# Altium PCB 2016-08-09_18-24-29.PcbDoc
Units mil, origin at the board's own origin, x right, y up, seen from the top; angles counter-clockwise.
Board outline 2000 x 2400 mil, 4 copper layers (Top Layer, MidLayer1, MidLayer2, Bottom Layer); 17 components, 8 nets, 39 pads, 72 vias.
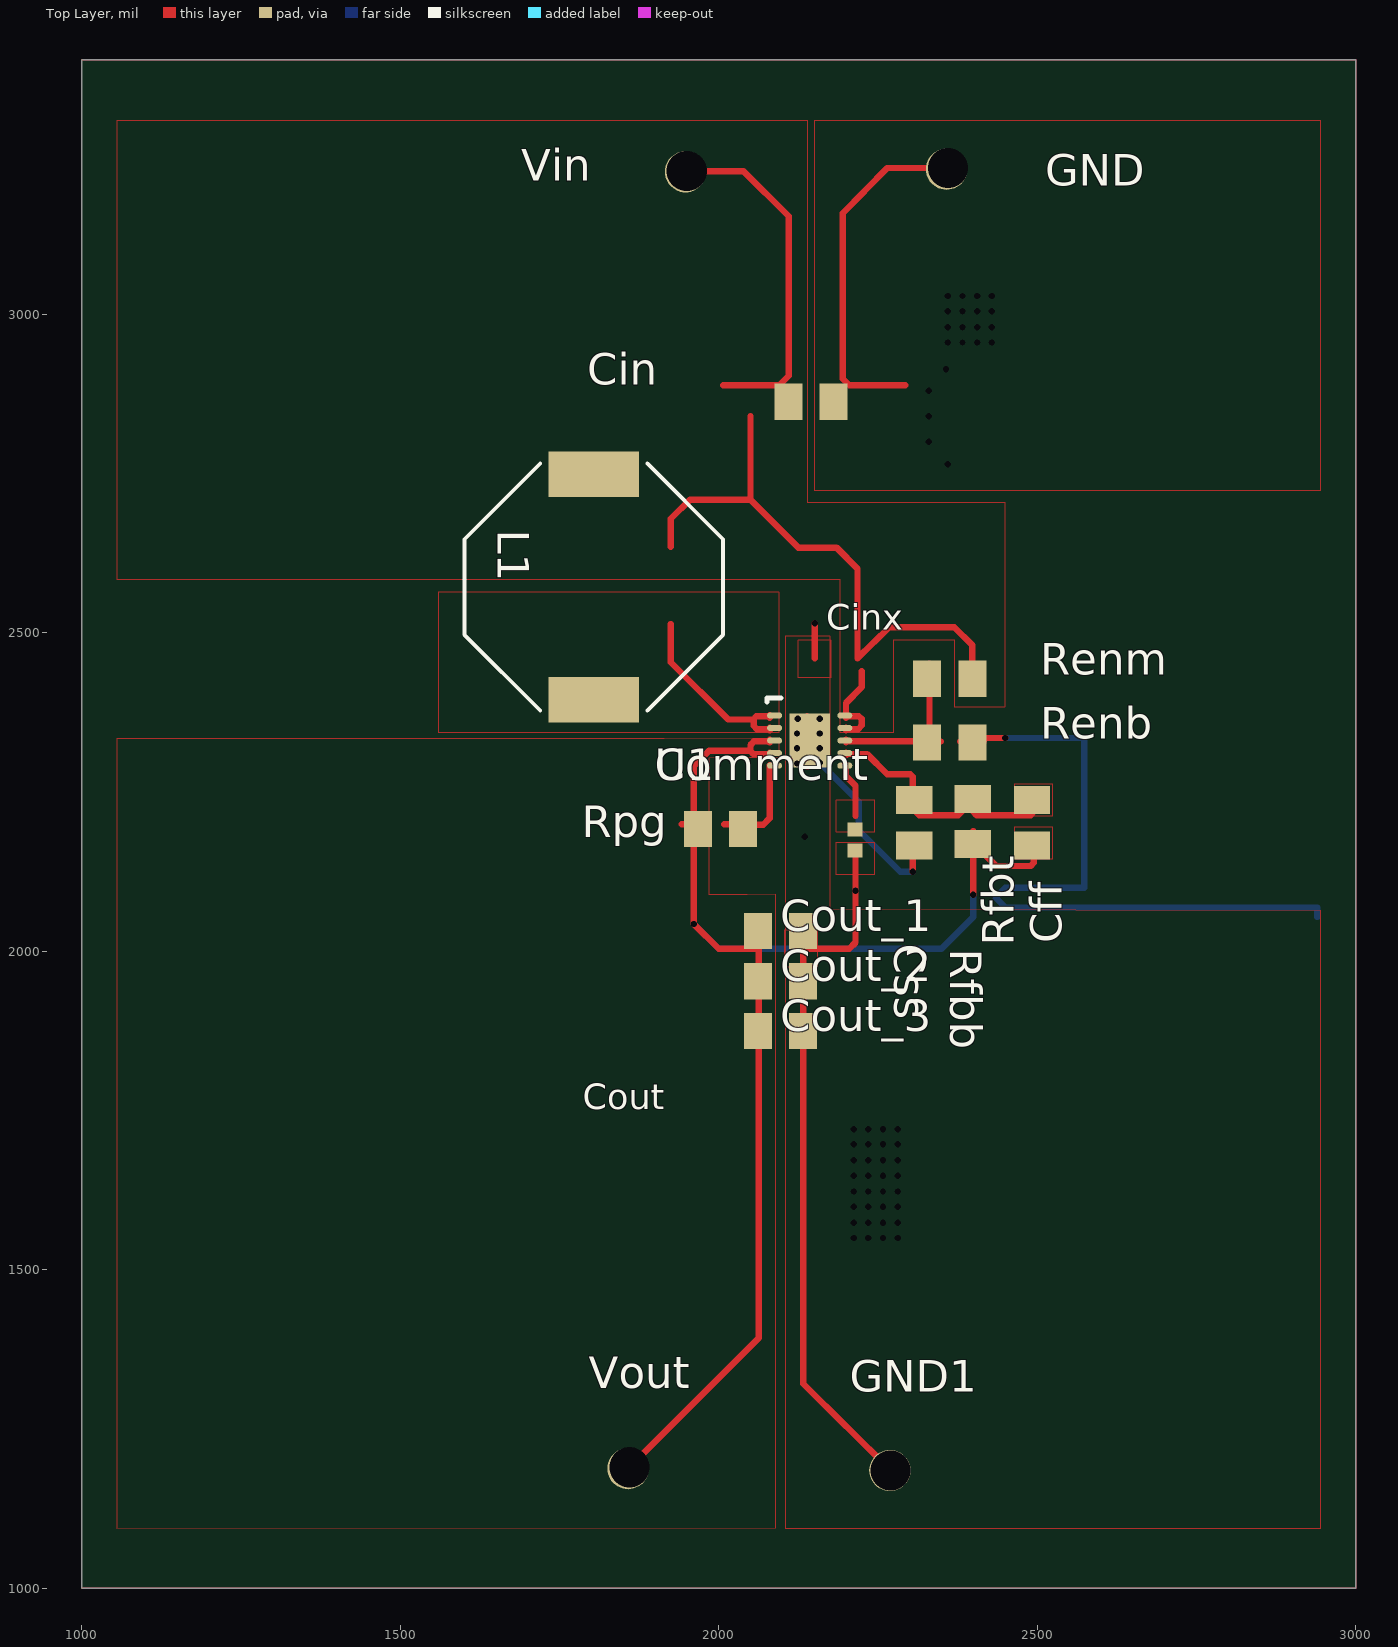
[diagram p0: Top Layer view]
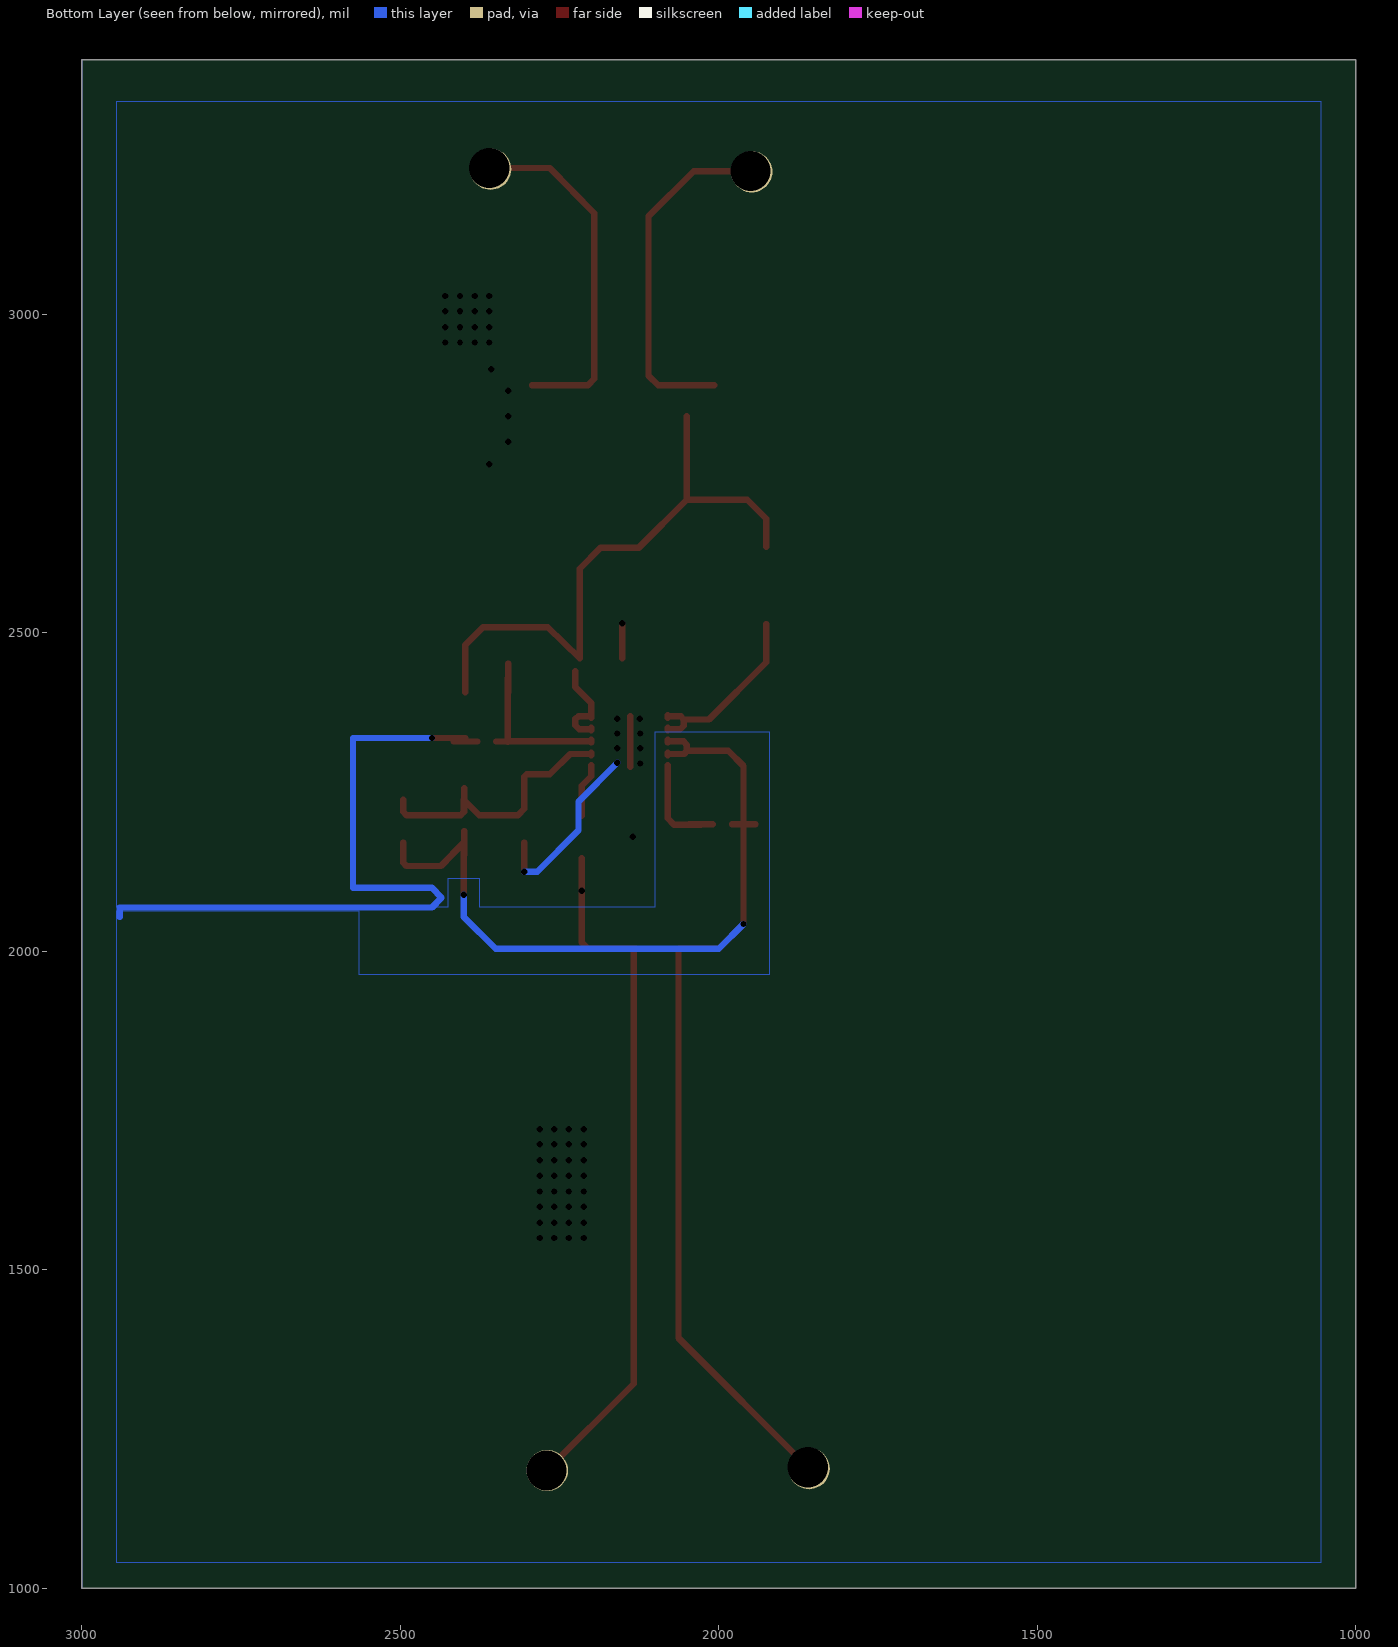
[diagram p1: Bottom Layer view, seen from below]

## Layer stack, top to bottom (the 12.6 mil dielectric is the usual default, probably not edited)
Top Layer: signal copper 1.4
Dielectric: core 12.6, FR-4, Dk 4.8
MidLayer1: signal copper 1.4
Dielectric: prepreg 12.6, FR-4, Dk 4.8
MidLayer2: signal copper 1.4
Dielectric: core 12.6, FR-4, Dk 4.8
Bottom Layer: signal copper 1.4

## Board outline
1000,1000 3000,1000 3000,3400 1000,3400

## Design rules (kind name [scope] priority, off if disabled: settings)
PlaneConnect [All] p0: scope1count=1 scope1_0_kind=Board scope1_0_value=Board scope2count=1 scope2_0_kind=Board scope2_0_value=Board commentlength=0 planeconnectstyle=Direct reliefexpansion=20 reliefentries=4 reliefconductorwidth=10 reliefairgap=10
PlaneConnect [All] p1: planeconnectstyle=Direct reliefexpansion=20 reliefentries=4 reliefconductorwidth=10 reliefairgap=10
PolygonConnect [All] p0: scope1count=1 scope1_0_kind=Board scope1_0_value=Board scope2count=1 scope2_0_kind=Board scope2_0_value=Board commentlength=0 connectstyle=Direct reliefconductorwidth=10 reliefentries=4 polygonreliefangle="90 Angle"
PolygonConnect [All] p1: connectstyle=Direct reliefconductorwidth=10 reliefentries=4 polygonreliefangle="90 Angle"

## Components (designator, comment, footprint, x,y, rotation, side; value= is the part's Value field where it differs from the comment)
Cff "" 0805 2492,2202 r90 top
Cin "" 0805 2145,2863 r0 top
Cout_1 "" 0805 2097,2032 r0 top
Cout_2 "" 0805 2097,1953 r0 top
Cout_3 "" 0805 2097,1875 r0 top
Css "" 0402 2214,2175 r270 top
GND "" TP-1502 2358,3228 r0 top
GND1 "" TP-1502 2269,1185 r0 top
L1 "" SRU1028 1804,2572 r270 top
Renb "" 0805 2363,2328 r0 top
Renm "" 0805 2363,2428 r0 top
Rfbb "" 0805 2307,2202 r270 top
Rfbt "" 0805 2399,2204 r90 top
Rpg "" 0805 2003,2192 r0 top
U1 "" DRC0010G 2143,2331 r0 top
Vin "" TP-1502 1948,3224 r0 top
Vout "" TP-1502 1858,1188 r0 top

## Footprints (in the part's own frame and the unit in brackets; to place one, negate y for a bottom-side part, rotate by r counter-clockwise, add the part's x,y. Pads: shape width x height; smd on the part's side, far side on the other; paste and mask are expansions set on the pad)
0402 [mil]
  rect 22x24 smd: 1(-16.5,0) 2(16.5,0)
0805 [mil]
  rect 44x57 smd: 1(-35.5,0) 2(35.5,0)
DRC0010G [mm]
  oval 0.6x0.24 smd: 1(-1.4,1) 2(-1.4,0.5) 3(-1.4,0) 4(-1.4,-0.5) 5(-1.4,-1) 6(1.4,-1) 7(1.4,-0.5) 8(1.4,0) 9(1.4,0.5) 10(1.4,1)
  rect 1.6x2.15 smd: 11(0,0)
  silkscreen extent -1.7,1.54 -1.15,1.7
SRU1028 [mil]
  rect 71x142 smd: 1(-177,0) 2(177,0)
  silkscreen extent -194,-203 194,203
TP-1502 [mil]
  round 65 / inner round 0 / far side round 65 hole 32: 1(0,0)

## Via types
v1: diameter 0, hole 10, Top Layer to Bottom Layer, 68 vias
v2: diameter 0, hole 63, Top Layer to Bottom Layer, 4 vias

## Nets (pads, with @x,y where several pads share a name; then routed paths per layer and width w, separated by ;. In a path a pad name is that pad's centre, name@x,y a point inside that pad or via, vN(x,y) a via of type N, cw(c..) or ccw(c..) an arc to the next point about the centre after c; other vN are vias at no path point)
0: Cin.2 Cout_1.2 Cout_2.2 Cout_3.2 Css.2 GND1.1 GND.1 Renb.2 Rfbb.2 U1.11 | length 3235.4
  Top Layer w10: Cout_1.2@2130,2004 Cout_1.2@2133,2004 ; U1.11@2139,2290 U1.11@2139,2369 ; 2151,2460 v1(2151,2515) ; 2215,2146 v1(2215,2095) 2215,2014 2205,2004 Cout_1.2@2133,2004 ; 2217,2889 2293,2889 ; 2255,2889 2205,2889 2195,2899 2195,3159 2265,3230 v2(2360,3230) ; v2(2270,1185) 2133,1321 Cout_1.2@2133,2004 ; v1(2305,2125) Rfbb.2@2305,2171 ; Renb.2@2379,2329.5 Renb.2@2416,2329.5 ; Renb.2@2398,2335 v1(2450,2335)
  Bottom Layer w10: v1(2159,2296) 2220,2235 2220,2190 2285,2125 v1(2305,2125) ; v1(2450,2335) 2574,2335 2574,2100 2450,2100 2435,2084 2450,2069 2940,2069 2940,2054
  other v1: 2212,1550 2235,1550 2258,1550 2281,1550 2212,1574 2235,1574 2258,1574 2281,1574 2212,1599 2235,1599 2258,1599 2281,1599 2212,1623 2235,1623 2258,1623 2281,1623 2212,1648 2235,1648 2258,1648 2281,1648 2212,1672 2235,1672 2258,1672 2281,1672 2212,1697 2235,1697 2258,1697 2281,1697 2212,1721 2235,1721 2258,1721 2281,1721 2135,2180 2123,2295 2123,2319 2159,2319 2123,2342 2159,2342 2124,2365 2159,2365 2360,2765 2330,2800 2330,2840 2330,2880 2357,2914 2360,2956 2383,2956 2406,2956 2429,2956 2360,2980 2383,2980 2406,2980 2429,2980 2360,3005 2383,3005 2406,3005 2429,3005 2360,3029 2383,3029 2406,3029 2429,3029
1: Cin.1 L1.1 Renm.2 U1.9 U1.10 Vin.1 | length 1714.6
  Top Layer w10: 1925,2635 1925,2679 1955,2709 2050,2709 ; v2(1950,3225) 2039,3225 2110,3154 2110,2904 2095,2889 2045,2889 ; 2007,2889 2083,2889 ; 2050,2840 2050,2709 ; U1.9@2200,2347 U1.9@2200,2351 ; U1.9@2200,2349 2219,2349 2225,2355 2225,2365 2220,2369 2200,2369 2200,2390 2225,2415 2225,2440 ; U1.10@2200,2367 U1.10@2200,2371 ; Renm.2@2397.5,2407 Renm.2@2397.5,2452 ; Renm.2@2398,2429 2398,2481 2370,2509 2268,2509 2218,2460 2218,2601 2185,2634 2125,2634 2050,2709
2: Cff.1 Cout_1.1 Cout_2.1 Cout_3.1 Rfbt.1 Rpg.1 U1.3 U1.4 Vout.1 | length 2257.2
  Top Layer w10: v2(1860,1190) 2063,1393 2063,2004 2000,2004 v1(1961,2043) 1961,2199 1961,2291 1985,2315 2050,2315 ; 1942,2199.5 Rpg.1@1979,2199.5 ; U1.4@2080,2308 U1.4@2080,2312 ; U1.4@2080,2310 2054,2310 2050,2315 ; U1.3@2080,2328 U1.3@2080,2332 ; U1.3@2080,2330 2055,2330 2055,2329 2050,2324 2050,2315 ; Rfbt.1@2399.5,2152 Rfbt.1@2399.5,2189 ; v1(2400,2089) 2400,2171 2436,2134 2490,2134 2495,2139 Cff.1@2495,2171
  Bottom Layer w10: v1(1961,2043) 2000,2004 2350,2004 2400,2054 v1(2400,2089)
5: L1.2 U1.1 U1.2 | length 299.8
  Top Layer w10: 1925,2514 1925,2454 2015,2364 2055,2364 ; U1.2@2080,2347 U1.2@2080,2351 ; U1.2@2080,2349 2060,2349 2055,2354 2055,2364 ; U1.1@2080,2367 U1.1@2080,2371 ; U1.1@2080,2369 2059,2369 2055,2364
7: Renb.1 Renm.1 U1.8 | length 317
  Top Layer w10: U1.8@2200,2328 U1.8@2200,2332 ; U1.8@2200,2330 Renb.1@2331,2330 ; Renb.1@2312,2329.5 Renb.1@2349,2329.5 ; Renm.1@2330.5,2407 Renm.1@2330.5,2452 ; Renb.1@2331,2329 Renm.1@2331,2429
8: Css.1 U1.6 | length 87.2
  Top Layer w10: U1.6@2200,2288 U1.6@2200,2292 ; U1.6@2200,2290 2200,2275 2215,2260 2215,2213
9: Rpg.2 U1.5 | length 178.1
  Top Layer w10: 2009,2199.5 Rpg.2@2046,2199.5 ; Rpg.2@2028,2199 2070,2199 2080,2209 U1.5@2080,2290 ; U1.5@2080,2288 U1.5@2080,2292
11: Cff.2 Rfbb.1 Rfbt.2 U1.7 | length 457.1
  Top Layer w10: U1.7@2200,2308 U1.7@2200,2312 ; U1.7@2200,2310 2233,2310 2265,2278 2301,2278 2305,2274 2305,2238 2305,2224 2315,2214 2376,2214 2400,2238 2400,2219 2405,2214 2490,2214 2495,2219 Cff.2@2495,2238 ; Rfbt.2@2399.5,2219 Rfbt.2@2399.5,2256

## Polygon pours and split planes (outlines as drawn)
0 on Bottom Layer " " (solid, pour order 9): 2945,3335 1055,3335 1055,1040 2945,1040 2945,2064 2565,2064 2565,1964 1920,1964 1920,2344 2100,2344 2100,2069 2375,2069 2375,2114 2425,2114 2425,2069 2945,2069
8 on Top Layer " " (solid, pour order 0): 2185,2187 2185,2238 2244,2238 2244,2187
11 on Top Layer " " (solid, pour order 1): 2465,2212 2465,2263 2524,2263 2524,2212
2 on Top Layer " " (solid, pour order 2): 2465,2145 2465,2196 2524,2196 2524,2145
5 on Top Layer " " (solid, pour order 3): 2095,2344 2095,2564 1560,2564 1560,2344
1 on Top Layer " " (solid, pour order 4): 2275,2344 2275,2489 2370,2489 2370,2384 2450,2384 2450,2704 2140,2704 2140,3304 1055,3304 1055,2584 2190,2584 2190,2344
2 on Top Layer " " (solid, pour order 5): 2095,2335 1915,2334 1055,2334 1055,1094 2090,1095 2090,2090 2045,2089 1985,2089 1985,2304 2045,2305 2095,2305
0 on Top Layer " " (solid, pour order 6): 2185,2120 2185,2171 2244,2171 2244,2120
0 on Top Layer " " (solid, pour order 7): 2104,1975 2104,2034 2155,2034 2155,1975
0 on Top Layer " " (solid, pour order 8): 2125,2430 2125,2489 2176,2489 2176,2430
0 on Top Layer " " (solid, pour order 10): 2945,3304 2150,3304 2150,2724 2945,2724
0 on Top Layer " " (solid, pour order 11): 2105,2495 2105,1094 2945,1094 2945,2064 2175,2065 2175,2495

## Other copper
Multi-Layer:
  the board outline again, w1

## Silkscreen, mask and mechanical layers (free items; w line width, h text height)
Top Overlay:
  text "Cinx" at 2169,2505 h40
  text "Cout" at 1787,1752 h40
